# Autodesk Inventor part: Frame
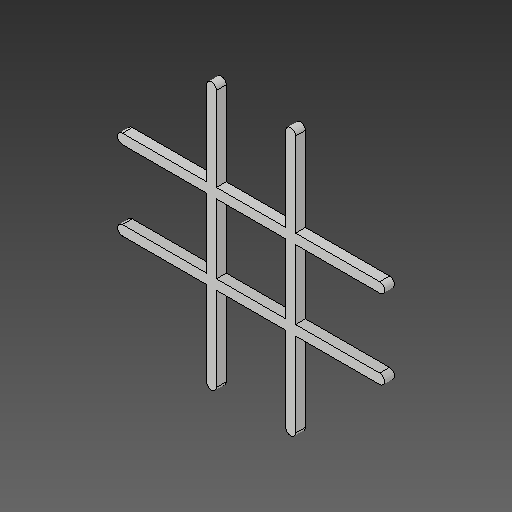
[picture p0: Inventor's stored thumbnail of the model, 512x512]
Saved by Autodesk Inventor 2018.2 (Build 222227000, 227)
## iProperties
Created: 2018-03
Part Number: Frame
Material: Generic
Document SubType Name: Modeling
Designer: PeterMaxwell-Stewart
Mass: 12.8927 g
Surface Area: 102.712 cm^2
Volume: 12.8927 cm^3
Density: 1 g/cm^3
Appearance: Default
Author: PeterMaxwell-Stewart
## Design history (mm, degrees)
derived "O's and X's.ipt"
feature "Frame::O's and X's.ipt" dims "d0" = 10
tag "TaggingFeature1"
body "Solid1"
